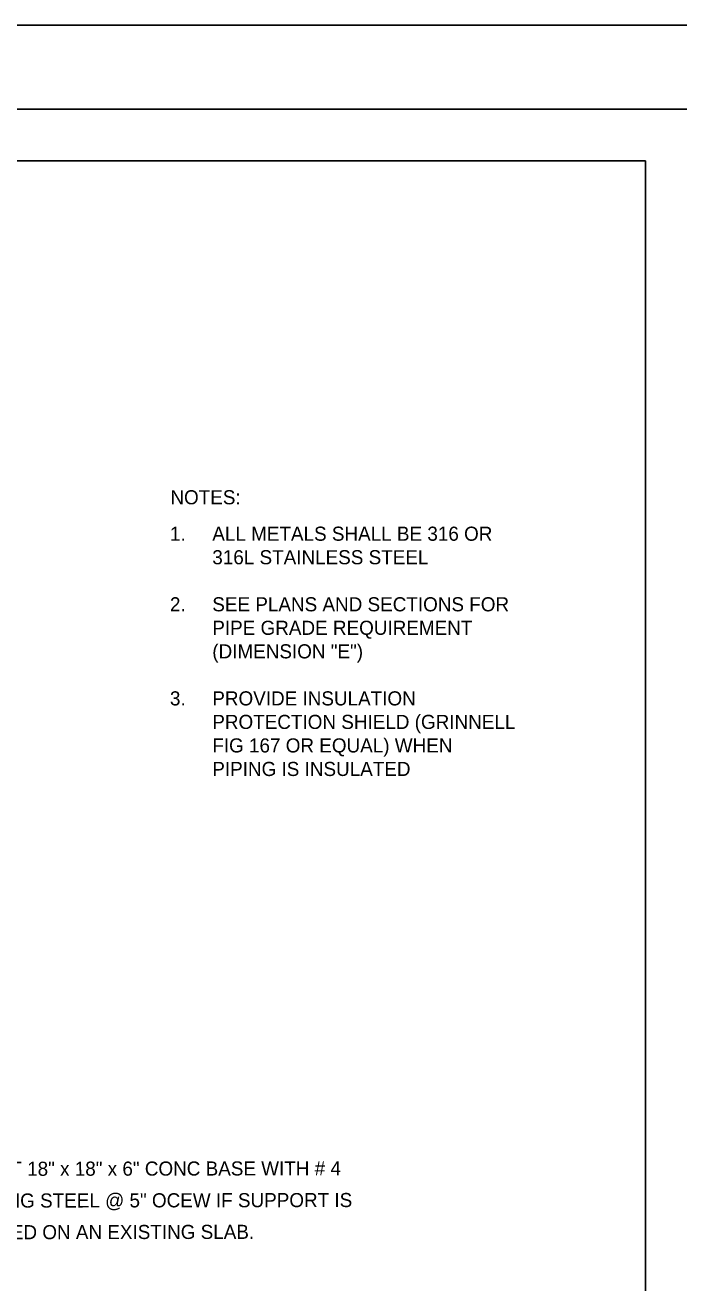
# Model space of a CAD drawing. Extents: x 2147138 to 2147698, y 2147153 to 2147515.
# Drawn here: x 2147237.7 to 2147293.3, y 2147408.1 to 2147515.1 of the extents above; entities that cross this region are included whole.
import ezdxf

# ---------------------------------------------------------------- set-up
doc = ezdxf.new("R2010")
doc.units = 0
for name, color, linetype in [('CONSTRUCTION_CLASS', 7, 'Continuous'), ('G-ANNO-TEXT-LW10', 7, 'Continuous'), ('G-DETL-ANNO-LW10', 7, 'Continuous'), ('PATTERN_CLASS', 7, 'Continuous')]:
    doc.layers.add(name, color=color, linetype=linetype)

msp = doc.modelspace()

# ---------------------------------------------------------------- linework, layer by layer
at = {"layer": 'CONSTRUCTION_CLASS'}
for p, q in [((2147697.66, 2147515.08), (2147137.79, 2147515.08)), ((2147160.2, 2147507.94), (2147689.06, 2147507.94))]:
    msp.add_line(p, q, dxfattribs=at)
at = {"layer": 'PATTERN_CLASS'}
for p, q in [((2147290.48, 2147503.54), (2147166.29, 2147503.54)), ((2147290.48, 2147351.27), (2147290.48, 2147503.54))]:
    msp.add_line(p, q, dxfattribs=at)

# ---------------------------------------------------------------- texts
at = {"layer": 'G-ANNO-TEXT-LW10'}
for s, p in [('1.', (2147250.06, 2147471.24)), ('ALL METALS SHALL BE 316 OR ', (2147253.66, 2147471.24)), ('316L STAINLESS STEEL', (2147253.66, 2147469.24)), ('2.', (2147250.06, 2147465.24)), ('SEE PLANS AND SECTIONS FOR ', (2147253.66, 2147465.24)), ('PIPE GRADE REQUIREMENT ', (2147253.66, 2147463.24)), ('(DIMENSION "E")', (2147253.66, 2147461.24)), ('3.', (2147250.06, 2147457.24)), ('PROVIDE INSULATION ', (2147253.66, 2147457.24)), ('PROTECTION SHIELD (GRINNELL ', (2147253.66, 2147455.24)), ('FIG 167 OR EQUAL) WHEN ', (2147253.66, 2147453.24)), ('PIPING IS INSULATED', (2147253.66, 2147451.24))]:
    msp.add_text(s, height=1.2, dxfattribs=at).set_placement(p)
at = {"layer": 'G-DETL-ANNO-LW10'}
msp.add_text('NOTES:', height=1.2, dxfattribs=at).set_placement((2147250.1, 2147474.34))
for s, p in [('CONSTRUCT 18" x 18" x 6" CONC BASE WITH # 4', (2147227.4, 2147417.23)), ('REINFORCING STEEL @ 5" OCEW IF SUPPORT IS', (2147227.34, 2147414.53)), ('NOT LOCATED ON AN EXISTING SLAB.', (2147227.35, 2147411.84))]:
    msp.add_text(s, height=1.2, rotation=0.0896, dxfattribs=at).set_placement(p)

doc.saveas('drawing.dxf')
